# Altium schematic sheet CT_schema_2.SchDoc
size 283 x 135 mm
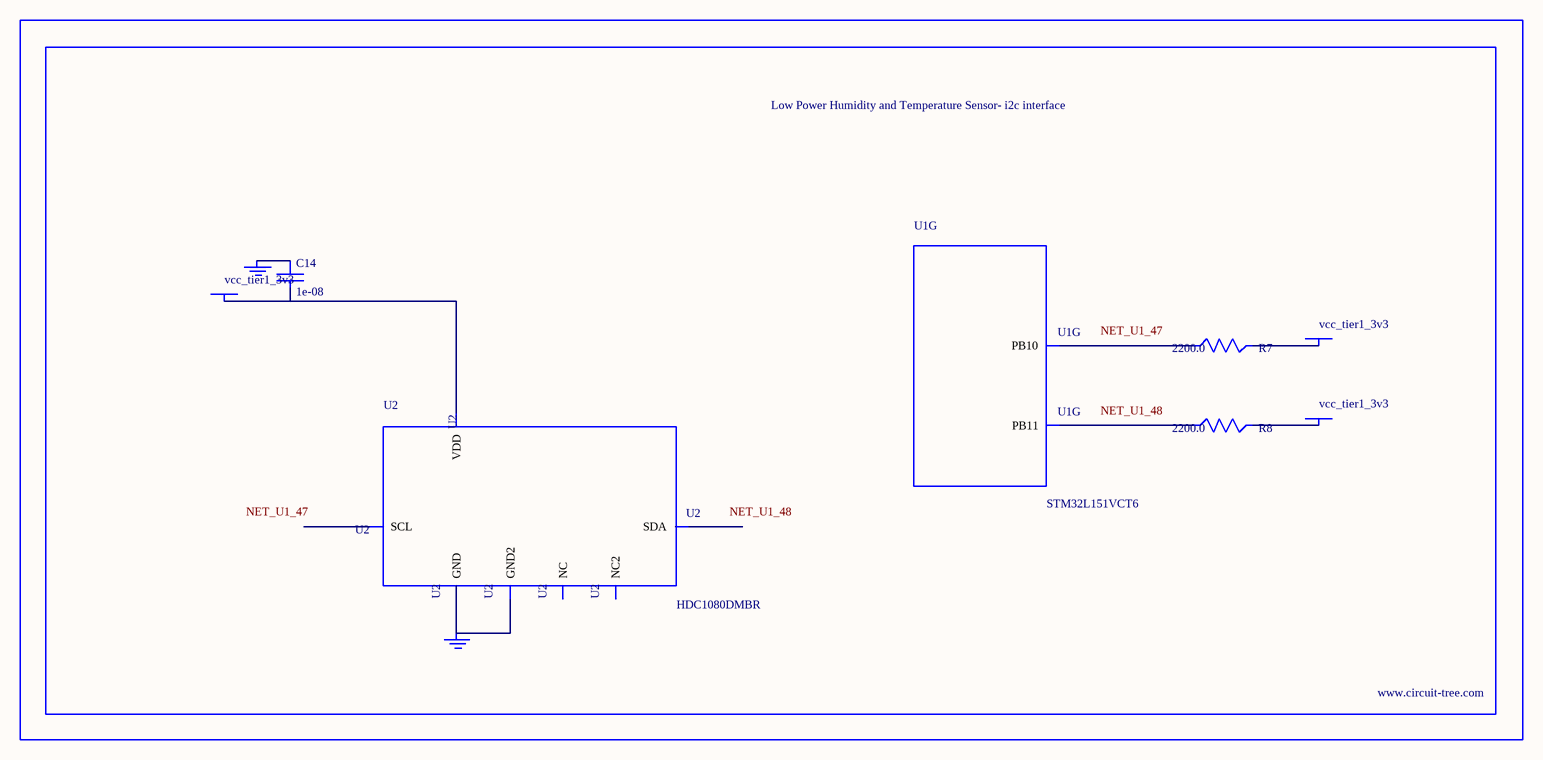
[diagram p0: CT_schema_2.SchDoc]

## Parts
BORDER1  (no value)
C14  1e-08  [C0402]
GND_INSTANCE_1_0  (no value)
GND_INSTANCE_1_1  (no value)
POWER_INSTANCE_1_0  vcc_tier1_3v3
POWER_INSTANCE_1_1  vcc_tier1_3v3
POWER_INSTANCE_1_2  vcc_tier1_3v3
R7  2200.0  [R0603]
R8  2200.0  [R0603]
U1  STM32L151VCT6  [LQFP100]  (part G of 11)
U2  HDC1080DMBR  [WSON-6]

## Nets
NetC14_1: C14.1 GND_INSTANCE_1_0.0(GND)
NetC14_2: C14.2 POWER_INSTANCE_1_0.0(PWR) U2.5(VDD)
NetGND_INSTANCE_1_1_0: GND_INSTANCE_1_1.0(GND) U2.2(GND) U2.PAD(GND2)
NetPOWER_INSTANCE_1_1_0: POWER_INSTANCE_1_1.0(PWR) R7.2
NetPOWER_INSTANCE_1_2_0: POWER_INSTANCE_1_2.0(PWR) R8.2
NetR7_1: R7.1 U1.47(PB10)
NetR8_1: R8.1 U1.48(PB11)

Not connected (* = marked no-connect by the designer): U2 1(SDA) 3(NC) 4(NC2) 6(SCL)

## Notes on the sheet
- Labels drawn without touching a wire or pin: NET_U1_47, NET_U1_48

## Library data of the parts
BORDER1 = BORDER_PAGE1
C14 = C0402C103K3RAC
GND_INSTANCE_1_0 GND_INSTANCE_1_1 = GND
POWER_INSTANCE_1_0-POWER_INSTANCE_1_2 = PWR
R7 R8 = RC0603JR-072K2L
